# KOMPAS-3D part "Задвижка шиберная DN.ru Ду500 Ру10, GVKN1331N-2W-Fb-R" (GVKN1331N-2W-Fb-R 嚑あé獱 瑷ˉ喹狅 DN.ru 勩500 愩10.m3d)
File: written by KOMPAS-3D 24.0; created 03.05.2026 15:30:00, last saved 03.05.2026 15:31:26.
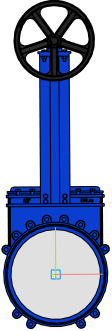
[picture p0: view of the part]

Document properties: Автор: DN.ru; Полное имя файла: C:\Работа\GVKN1331N-2W-Fb-R Задвижка шиберная DN.ru Ду400-600 Ру10\DN500\GVKN1331N-2W-Fb-R Задвижка шиберная DN.ru Ду500 Ру10.m3d

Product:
- Part/product: Задвижка шиберная DN.ru Ду500 Ру10  | designation GVKN1331N-2W-Fb-R
    Масса: 195
    Раздел спецификации: Прочие изделия
    Примечание: D040-07829

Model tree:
1. Операция без истории:1

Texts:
  GVKN1331N-2W-Fb-R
